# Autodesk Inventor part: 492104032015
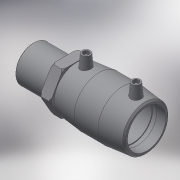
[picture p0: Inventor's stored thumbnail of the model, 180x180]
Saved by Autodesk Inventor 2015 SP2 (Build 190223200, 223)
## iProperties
Created: 2017-06
Part Number: 492104032015
Material: Generic
Description: PLASSON Male Transition Coupler 32 x 1.1/2"
Document SubType Name: Modeling
Designer: KIM
Mass: 106.815 g
Surface Area: 376.783 cm^2
Volume: 106.815 cm^3
Density: 1 g/cm^3
Appearance: Default
Author: KIM
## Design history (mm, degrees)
derived "492104.ipt"
feature "Solid1::492104.ipt"
tag "TaggingFeature1"
body "Solid1"
other parameters: "d0" = 88, "d1" = 32, "d2" = 44, "d3" = 42, "d4" = 29.33333, "d5" = 39.6, "d6" = 30.4, "d7" = 32, "d8" = 168 deg, "d10" = 16.8, "d11" = 5.6, "d29" = 42, "d30" = 14, "d31" = 30.8, "d34" = 5 deg, "d41" = 4, "d42" = 14, "d43" = 0, "d48" = 3, "d49" = 0, "d57" = 23, "d58" = 47.803, "d59" = 38.2424, "d60" = 32.4, "d61" = 57.2, "d62" = 0.95606, "d65" = 1.32, "d70" = 0.1, "d71" = 36, "d72" = 9, "d73" = 16.8, "d75" = 0, "d_" = 32, "L_" = 124, "L_1" = 42, "D_1" = 44, "A_" = 42, "d_2" = 12, "L_2" = 36, "D_" = 23, "R_" = 47.803
